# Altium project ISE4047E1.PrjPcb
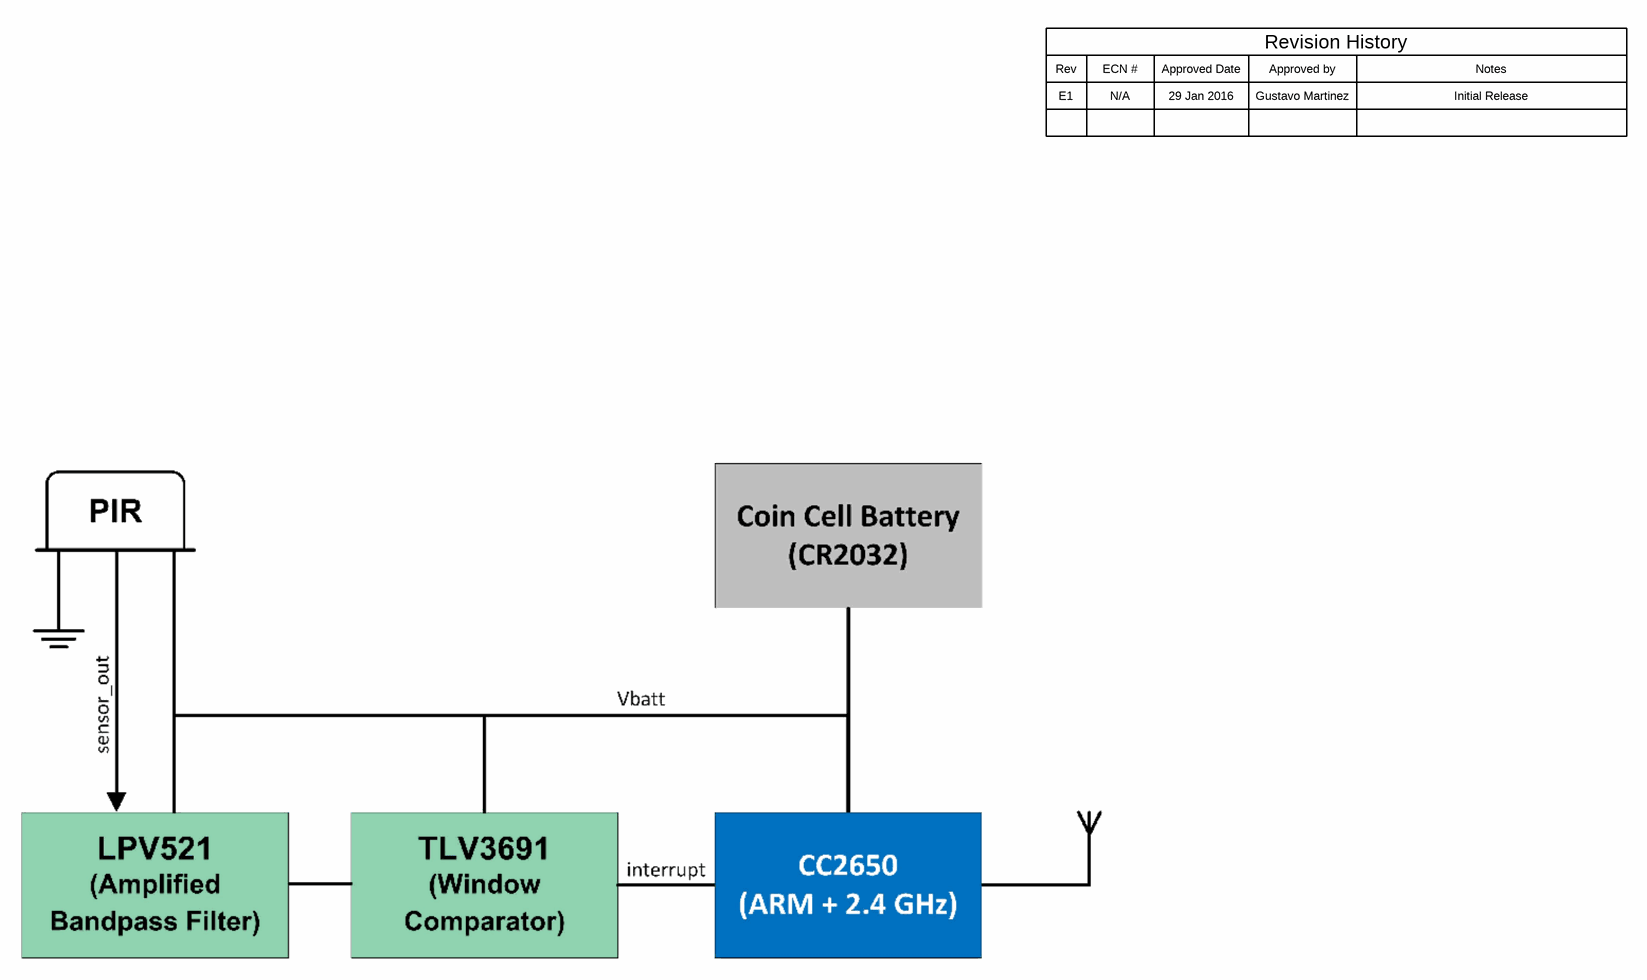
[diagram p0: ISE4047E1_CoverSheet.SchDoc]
CopyrightYear: 2016; EVM_Orderable: N/A; PCB_Layout: Krypton Solutions; PCB_Rev: E1; PRJ_Customer: Public Release; PRJ_Engineer: Gustavo Martinez; PRJ_Number: ISE4047; PRJ_Title: Wireless PIR Motion Detector w/ BLE Connectivity; SCH_Rev: E1; TechSupport: http://www.ti.com/support; TID: TIDA-00759
4 sheets, 131 parts. Net scope: global (net labels, ports and power ports of the same name join across sheets).
Board file: ISE4047E1_TID.PcbDoc
Sheets:
  ISE4047E1_CoverSheet.SchDoc
  ISE4047E1_POWER_PIR.SchDoc
  ISE4047E1_MCU.SchDoc
  ISE4047E1_TID_Hardware.SchDoc

## Sheet ISE4047E1_CoverSheet.SchDoc: Cover Sheet
size 431 x 279 mm; Date: Not shown in title block; ApprovedBy: Not shown in title block; CheckedBy: Not shown in title block; Author: Not shown in title block; CompanyName: Not shown in title block; DrawnBy: Gustavo Martinez; Engineer: Not shown in title block; Organization: Not shown in title block; Address1: Not shown in title block; Address2: Not shown in title block; Address3: Not shown in title block; Address4: Not shown in title block; DocumentNumber: 1; Revision: Use project parameter SCH_Rev; SheetNumber: 1; SheetTotal: 4; PageSetup: Record=PageOptions¦CenterHorizontal=True¦CenterVertical=True¦PrintScale=0.64¦XCorrection=1.00¦YCorrection=1.00¦PrintKind=0¦BorderSize=5000000¦LeftOffset=0¦BottomOffset=0¦Orientation=2¦PaperLength=1000¦PaperWidth=1000¦Scale=100¦PaperSource=15¦PrintQuality=1200¦MediaType=1¦DitherType=10¦PrintScaleMode=1¦PaperKind=Letter¦PaperIndex=1

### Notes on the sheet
- Rev
- E1
- ECN #
- N/A
- Approved Date
- 29 Jan 2016
- Approved by
- Gustavo Martinez
- Revision History
- Notes
- Initial Release

## Sheet ISE4047E1_POWER_PIR.SchDoc: Power and PIR Sensor
size 431 x 279 mm; Date: Not shown in title block; ApprovedBy: Not shown in title block; CheckedBy: Not shown in title block; Author: Not shown in title block; CompanyName: Not shown in title block; DrawnBy: David Stout; Engineer: David Stout; Organization: Not shown in title block; Address1: Not shown in title block; Address2: Not shown in title block; Address3: Not shown in title block; Address4: Not shown in title block; DocumentNumber: 1; Revision: Use project parameter SCH_Rev; SheetNumber: 2; SheetTotal: 4; PageSetup: Record=PageOptions¦CenterHorizontal=True¦CenterVertical=True¦PrintScale=0.62¦XCorrection=1.00¦YCorrection=1.00¦PrintKind=0¦BorderSize=5000000¦LeftOffset=0¦BottomOffset=0¦Orientation=2¦PaperLength=1000¦PaperWidth=1000¦Scale=100¦PaperSource=15¦PrintQuality=600¦MediaType=1¦DitherType=10¦PrintScaleMode=1¦PaperKind=Letter (8.5 x 11")¦PaperIndex=1
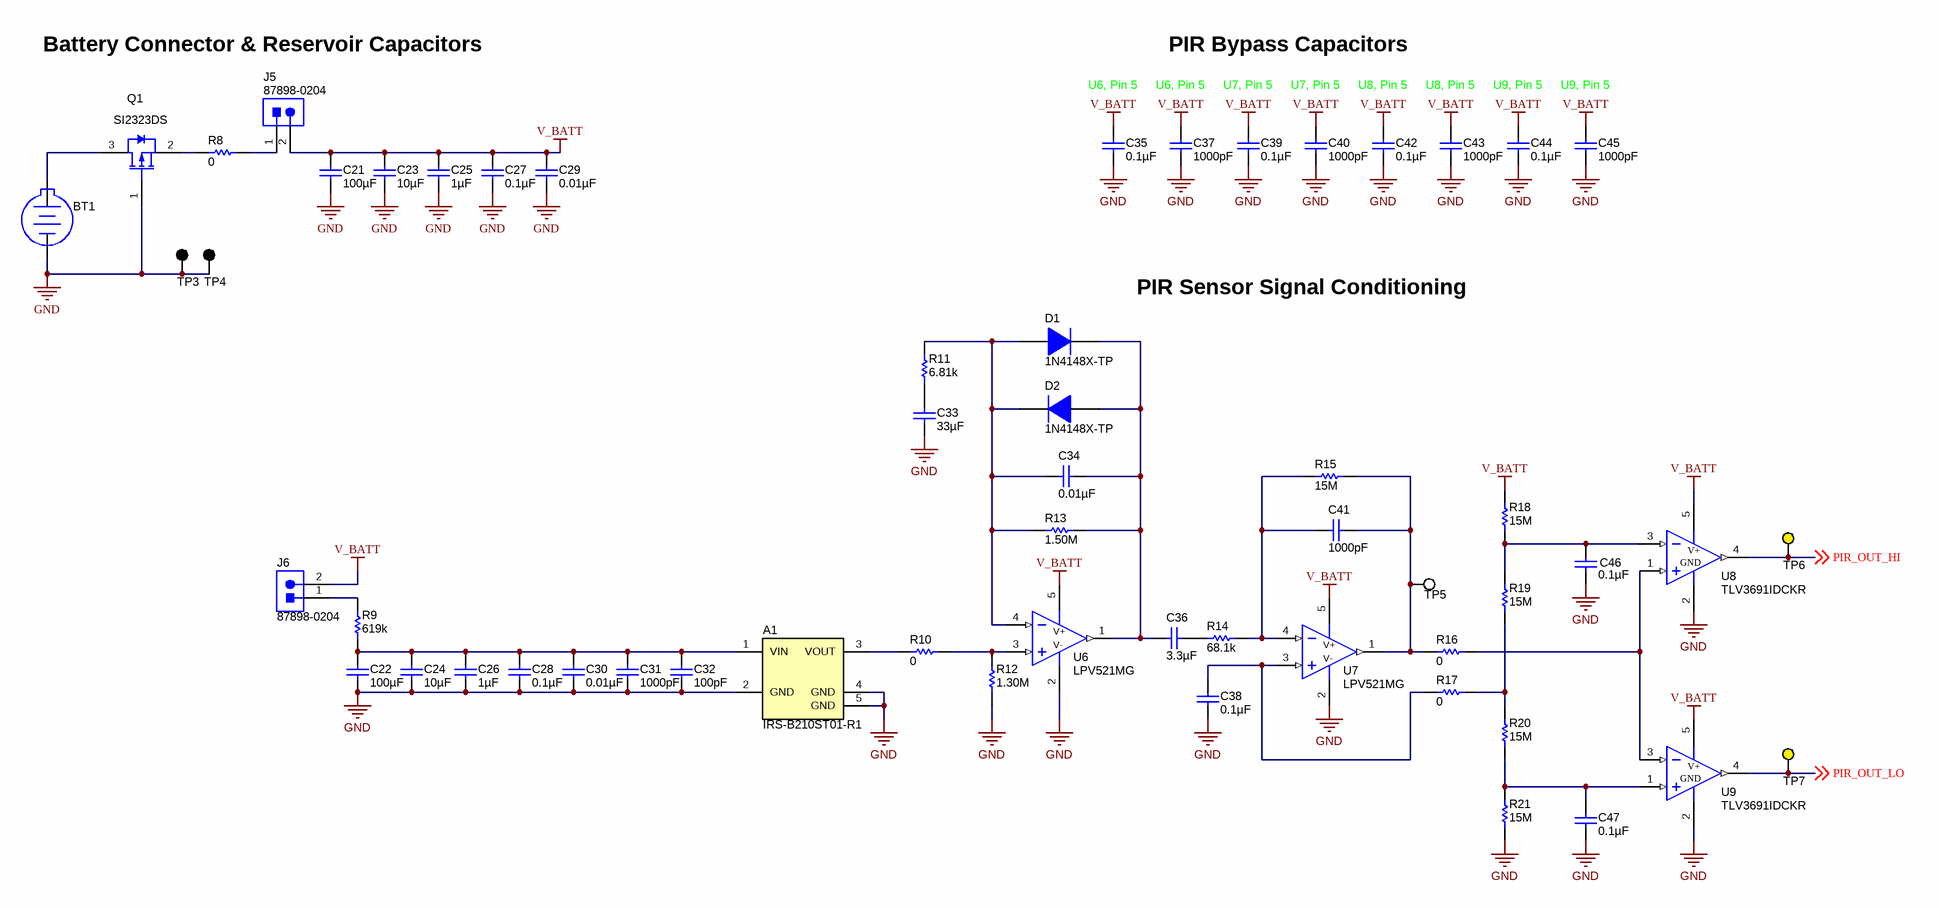
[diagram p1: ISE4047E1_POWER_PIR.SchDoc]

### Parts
A1  IRS-B210ST01-R1  [Murata_IRS-B210ST01]
BT1  BS-7  [BAT_BS-7]  (value not drawn)
C21  ValueDisplayed: 100µF  [1206_190]  (hidden comment: C3216X5R1A107M160AC)
C22  ValueDisplayed: 100µF  [1206_190]  (hidden comment: C3216X5R1A107M160AC)
C23  ValueDisplayed: 10µF  [0603]  (hidden comment: C1608X5R0J106M)
C24  ValueDisplayed: 10µF  [0402]  (hidden comment: GRM155R60J106ME44D)
C25  ValueDisplayed: 1µF  [0603]  (hidden comment: C1608X7R1C105K)
C26  ValueDisplayed: 1µF  [0402]  (hidden comment: C1005X5R1A105K050BB)
C27  ValueDisplayed: 0.1µF  [0402]  (hidden comment: C1005X7R1H104K050BB)
C28  ValueDisplayed: 0.1µF  [0402]  (hidden comment: C1005X7R1H104K050BB)
C29  ValueDisplayed: 0.01µF  [0402]  (hidden comment: C1005X7R1C103K050BA)
C30  ValueDisplayed: 0.01µF  [0402]  (hidden comment: C1005X7R1C103K050BA)
C31  ValueDisplayed: 1000pF  [0402]  (hidden comment: C1005X7R1H102K)
C32  ValueDisplayed: 100pF  [0402]  (hidden comment: C0402C101J3GACTU)
C33  ValueDisplayed: 33µF  [0805_HV]  (hidden comment: C2012X5R1A336M125AC)
C34  ValueDisplayed: 0.01µF  [0402]  (hidden comment: C1005X7R1E103K)
C35  ValueDisplayed: 0.1µF  [0402]  (hidden comment: C1005X7R1H104K)
C36  ValueDisplayed: 3.3µF  [0402]  (hidden comment: C1005X5R1A335K050BC)
C37  ValueDisplayed: 1000pF  [0402]  (hidden comment: C1005X7R1H102K)
C38  ValueDisplayed: 0.1µF  [0402]  (hidden comment: C1005X7R1H104K)
C39  ValueDisplayed: 0.1µF  [0402]  (hidden comment: C1005X7R1H104K)
C40  ValueDisplayed: 1000pF  [0402]  (hidden comment: C1005X7R1H102K)
C41  ValueDisplayed: 1000pF  [0402]  (hidden comment: C1005C0G1E102J)
C42  ValueDisplayed: 0.1µF  [0402]  (hidden comment: C1005X7R1H104K)
C43  ValueDisplayed: 1000pF  [0402]  (hidden comment: C1005X7R1H102K)
C44  ValueDisplayed: 0.1µF  [0402]  (hidden comment: C1005X7R1H104K)
C45  ValueDisplayed: 1000pF  [0402]  (hidden comment: C1005X7R1H102K)
C46  ValueDisplayed: 0.1µF  [0402]  (hidden comment: C1005X7R1H104K)
C47  ValueDisplayed: 0.1µF  [0402]  (hidden comment: C1005X7R1H104K)
D1  1N4148X-TP  [SOD-523]
D2  1N4148X-TP  [SOD-523]
J5  87898-0204  [Molex_87898-0204]
J6  87898-0204  [Molex_87898-0204]
Q1  SI2323DS  [SOT-23]
R8  ValueDisplayed: 0  [0805_HV]  (hidden comment: CRCW08050000Z0EA)
R9  ValueDisplayed: 619k  [0402]  (hidden comment: CRCW0402619KFKED)
R10  ValueDisplayed: 0  [0402]  (hidden comment: CRCW04020000Z0ED)
R11  ValueDisplayed: 6.81k  [0402]  (hidden comment: CRCW04026K81FKED)
R12  ValueDisplayed: 1.30M  [0402]  (hidden comment: CRCW04021M30FKED)
R13  ValueDisplayed: 1.50M  [0402]  (hidden comment: CRCW04021M50FKED)
R14  ValueDisplayed: 68.1k  [0402]  (hidden comment: CRCW040268K1FKED)
R15  ValueDisplayed: 15M  [0805_HV]  (hidden comment: RMCF0805JT15M0)
R16  ValueDisplayed: 0  [0402]  (hidden comment: CRCW04020000Z0ED)
R17  ValueDisplayed: 0  [0402]  (hidden comment: CRCW04020000Z0ED)
R18  ValueDisplayed: 15M  [0805_HV]  (hidden comment: RMCF0805JT15M0)
R19  ValueDisplayed: 15M  [0805_HV]  (hidden comment: RMCF0805JT15M0)
R20  ValueDisplayed: 15M  [0805_HV]  (hidden comment: RMCF0805JT15M0)
R21  ValueDisplayed: 15M  [0805_HV]  (hidden comment: RMCF0805JT15M0)
TP3  5001  [Keystone5001]  (value not drawn)
TP4  5001  [Keystone5001]  (value not drawn)
TP5  5015  [Testpoint_Keystone_Miniature]  (value not drawn)
TP6  5004  [Keystone5004]  (value not drawn)
TP7  5004  [Keystone5004]  (value not drawn)
U6  LPV521MG  [DCK0005A_N]
U7  LPV521MG  [DCK0005A_N]
U8  TLV3691IDCKR  [DCK0005A_N]
U9  TLV3691IDCKR  [DCK0005A_N]

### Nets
GND: A1.2(GND) A1.4(GND) A1.5(GND) BT1.2(-) C21.2 C22.2 C23.2 C24.2 C25.2 C26.2 C27.2 C28.2 C29.2 C30.2 C31.2 C32.2 C33.2 C35.1 C37.2 C38.2 C39.1 C40.2 C42.1 C43.2 C44.1 C45.2 C46.2 C47.2 Q1.1(G) R12.1 R21.1 TP3.1 TP4.1 U6.2(V-) U7.2(V-) U8.2(GND) U9.2(GND)
V_BATT: C21.1 C23.1 C25.1 C27.1 C29.1 C35.2 C37.1 C39.2 C40.1 C42.2 C43.1 C44.2 C45.1 J5.2 J6.2 R18.2 U6.5(V+) U7.5(V+) U8.5(V+) U9.5(V+)
PIR_OUT_HI: TP6.1 U8.4(OUT) ; off-sheet PIR_OUT_HI
PIR_OUT_LO: TP7.1 U9.4(OUT) ; off-sheet PIR_OUT_LO
NetA1_1: A1.1(VIN) C22.1 C24.1 C26.1 C28.1 C30.1 C31.1 C32.1 R9.1
NetA1_3: A1.3(VOUT) R10.1
NetBT1_1: BT1.1(+) Q1.3(D)
NetC33_1: C33.1 R11.1
NetC34_1: C34.1 C36.2 D1.1(K) D2.2(A) R13.2 U6.1(OUT)
NetC34_2: C34.2 D1.2(A) D2.1(K) R11.2 R13.1 U6.4(IN-)
NetC36_1: C36.1 R14.1
NetC38_1: C38.1 R17.1 U7.3(IN+)
NetC41_1: C41.1 R15.2 R16.1 TP5.1 U7.1(OUT)
NetC41_2: C41.2 R14.2 R15.1 U7.4(IN-)
NetC46_1: C46.1 R18.1 R19.2 U8.3(IN-)
NetC47_1: C47.1 R20.1 R21.2 U9.1(IN+)
NetJ5_1: J5.1 R8.2
NetJ6_1: J6.1 R9.2
NetQ1_2: Q1.2(S) R8.1
NetR10_2: R10.2 R12.2 U6.3(IN+)
NetR16_2: R16.2 U8.1(IN+) U9.3(IN-)
NetR17_2: R17.2 R19.1 R20.2

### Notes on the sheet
- Battery Connector & Reservoir Capacitors
- PIR Bypass Capacitors
- U6, Pin 5
- U7, Pin 5
- U8, Pin 5
- U9, Pin 5
- PIR Sensor Signal Conditioning

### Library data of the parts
A1 = IRS-B210ST01-R1: Pyroelectric Infrared Sensors for Reflow Soldering, 3.6mVp-p, SMD; Manufacturer: MuRata; SymbolCreator: Altium; CompType: SENSOR
BT1 = BS-7: Battery Holder, CR2032, Retainer clip, TH; Manufacturer: Memory Protection Devices; SymbolCreator: a0412235
C21 C22 = C3216X5R1A107M160AC: CAP, CERM, 100 µF, 10 V, +/- 20%, X5R, 1206_190; Manufacturer: TDK; Polarized: N; CompType: Capacitor; Value: 100uF; U/M: EA; Cap_F: 0.0001; Tolerance_%: 20; Value1: Unknown; VDC_V: 10; Value2: 10V; TaMin_C: -55; TaMax_C: 85; Cap_Case: 1206; AEC Category: Q200
C23 = C1608X5R0J106M: CAP, CERM, 10 µF, 6.3 V, +/- 20%, X5R, 0603; Manufacturer: TDK; Polarized: N; CompType: Capacitor; Value: 10uF; U/M: EA; Cap_F: 0.00001; Tolerance_%: 20; ESR_ohm: 0.005; Value1: 0.005 ohm; VDC_V: 6.3; Value2: 6.3V; IRMS_A: 1.9; TaMin_C: -25; TaMax_C: 85; AEC Category: Q200
C24 = GRM155R60J106ME44D: CAP, CERM, 10 µF, 6.3 V, +/- 20%, X5R, 0402; Manufacturer: MuRata; Polarized: N; CompType: Capacitor; Value: 10uF; U/M: EA; Cap_F: 0.00001; Tolerance_%: 20; Value1: Unknown; VDC_V: 6.3; Value2: 6.3V; TaMin_C: -55; TaMax_C: 85; AEC Category: Q200
C25 = C1608X7R1C105K: CAP, CERM, 1 µF, 16 V, +/- 10%, X7R, 0603; Manufacturer: TDK; Polarized: N; CompType: Capacitor; Value: 1uF; U/M: EA; Cap_F: 0.000001; Tolerance_%: 10; ESR_ohm: 0.0057; Value1: 0.0057 ohm; VDC_V: 16; Value2: 16V; TaMin_C: -55; TaMax_C: 125; AEC Category: Q200
C26 = C1005X5R1A105K050BB: CAP, CERM, 1 µF, 10 V, +/- 10%, X5R, 0402; Manufacturer: TDK; Polarized: N; CompType: Capacitor; Value: 1uF; U/M: EA; Cap_F: 0.000001; Tolerance_%: 10; Value1: Unknown; Value2: 10V; TaMin_C: -55; TaMax_C: 85; AEC Category: Q200
C27 C28 = C1005X7R1H104K050BB: CAP, CERM, 0.1 µF, 50 V, +/- 10%, X7R, 0402; Manufacturer: TDK; Polarized: N; CompType: Capacitor; Value: 0.1uF; U/M: EA; Cap_F: 0.0000001; Tolerance_%: 10; Value1: Unknown; VDC_V: 50; Value2: 50V; TaMin_C: -55; TaMax_C: 125; AEC Category: Q200
C29 C30 = C1005X7R1C103K050BA: CAP, CERM, 0.01 µF, 16 V, +/- 10%, X7R, 0402; Manufacturer: TDK; Polarized: N; CompType: Capacitor; Value: 0.01uF; U/M: EA; Cap_F: 0.00000001; Tolerance_%: 10; ESR_ohm: 0.0623; Value1: 0.0623 ohm; VDC_V: 16; Value2: 16V; TaMin_C: -55; TaMax_C: 125; AEC Category: Q200
C31 C37 C40 C43 C45 = C1005X7R1H102K: CAP, CERM, 1000 pF, 50 V, +/- 10%, X7R, 0402; Manufacturer: TDK; Polarized: N; CompType: Capacitor; Value: 1000pF; U/M: EA; Cap_F: 0.000000001; Tolerance_%: 10; ESR_ohm: 0.2381; Value1: 0.2381 ohm; VDC_V: 50; Value2: 50V; TaMin_C: -55; TaMax_C: 125; AEC Category: Q200
C32 = C0402C101J3GACTU: CAP, CERM, 100 pF, 25 V, +/- 5%, C0G/NP0, 0402; Manufacturer: Kemet; Polarized: N; CompType: Capacitor; Value: 100pF; U/M: EA; Cap_F: 0.0000000001; Tolerance_%: 5; Value1: Unknown; VDC_V: 25; Value2: 25V; TaMin_C: -55; TaMax_C: 125; AEC Category: Q200
C33 = C2012X5R1A336M125AC: CAP, CERM, 33 µF, 10 V, +/- 20%, X5R, 0805; Manufacturer: TDK; Polarized: N; CompType: Capacitor; Value: 33uF; U/M: EA; Cap_F: 0.000033; Tolerance_%: 20; Value1: Unknown; VDC_V: 10; Value2: 10V; TaMin_C: -55; TaMax_C: 85; Cap_Case: 0805; AEC Category: Q200
C34 = C1005X7R1E103K: CAP, CERM, 0.01 µF, 25 V, +/- 10%, X7R, 0402; Manufacturer: TDK; Polarized: N; CompType: Capacitor; Value: 0.01uF; U/M: EA; Cap_F: 0.00000001; Tolerance_%: 10; ESR_ohm: 0.0623; Value1: 0.0623 ohm; VDC_V: 25; Value2: 25V; TaMin_C: -55; TaMax_C: 125; AEC Category: Q200
C35 C38 C39 C42 C44 C46 C47 = C1005X7R1H104K: CAP, CERM, 0.1 µF, 50 V, +/- 10%, X7R, 0402; Manufacturer: TDK; Polarized: N; CompType: Capacitor; Value: 0.1uF; U/M: EA; Cap_F: 0.0000001; Tolerance_%: 10; Value1: Unknown; VDC_V: 50; Value2: 50V; TaMin_C: -55; TaMax_C: 125; AEC Category: Q200
C36 = C1005X5R1A335K050BC: CAP, CERM, 3.3 µF, 10 V, +/- 10%, X5R, 0402; Manufacturer: TDK; Polarized: N; CompType: Capacitor; Value: 3.3uF; U/M: EA; Cap_F: 0.0000033; Tolerance_%: 10; Value1: Unknown; Value2: 10V; TaMin_C: -55; TaMax_C: 85; AEC Category: Q200
C41 = C1005C0G1E102J: CAP, CERM, 1000 pF, 25 V, +/- 5%, C0G/NP0, 0402; Manufacturer: TDK; Polarized: N; CompType: Capacitor; Value: 1000pF; U/M: EA; Cap_F: 0.000000001; Tolerance_%: 5; Value1: Unknown; VDC_V: 25; Value2: 25V; TaMin_C: -55; TaMax_C: 125; AEC Category: Q200
D1 D2 = 1N4148X-TP: Diode, Switching, 75 V, 0.3 A, SOD-523; Manufacturer: Micro Commercial Components; U/M: EA; Vf_V: 1.25; Value: 75V; Value1: 0.3A; Value2: 1.25V; Io_A: 0.3; Vr_V: 75; TJmax_C: 150; AEC Category: Q101
J5 J6 = 87898-0204: Header, 2.54 mm, 2x1, Gold, R/A, SMT; Manufacturer: Molex; SymbolCreator: a0412235; U/M: EA
Q1 = SI2323DS: MOSFET, P-CH, -20 V, -3.7 A, SOT-23; Manufacturer: Vishay-Siliconix; Alternate Manufacturer: None; U/M: EA; ChType: P; Value: -20V; Value1: 0.031 ohm; Rdson45_ohm: 0.031; Value2: 12.5 nC; QgTyp_nC: 12.5; Vgs_V: -8; AEC Category: Q101
R8 = CRCW08050000Z0EA: RES, 0, 5%, 0.125 W, 0805; Manufacturer: Vishay-Dale; CompType: Resistor; Value: 0; Value_Code: 0000; Tolerance_%: 5; Power_W: 0.125; Value2: 0.125W; VDC_V: 150; TempCo: 200 ppm/C; EIA_Code: E24; U/M: EA; AEC Category: Q200
R9 = CRCW0402619KFKED: RES, 619 k, 1%, 0.063 W, 0402; Manufacturer: Vishay-Dale; CompType: Resistor; Value: 619k; Res_ohm: 619000; Tolerance_%: 1; Power_W: 0.063; Value2: 0.063W; VDC_V: 50; TempCo: 100 ppm/C; EIA_Code: E96; U/M: EA; AEC Category: Q200
R10 R16 R17 = CRCW04020000Z0ED: RES, 0, 5%, 0.063 W, 0402; Manufacturer: Vishay-Dale; CompType: Resistor; Value: 0; Value_Code: 0000; Tolerance_%: 5; Power_W: 0.063; Value2: 0.063W; VDC_V: 50; TempCo: 200 ppm/C; EIA_Code: E24; U/M: EA; AEC Category: Q200
R11 = CRCW04026K81FKED: RES, 6.81 k, 1%, 0.063 W, 0402; Manufacturer: Vishay-Dale; CompType: Resistor; Value: 6.81k; Res_ohm: 6810; Value_Code: 6k81; Tolerance_%: 1; Power_W: 0.063; Value2: 0.063W; VDC_V: 50; TempCo: 100 ppm/C; EIA_Code: E96; U/M: EA; AEC Category: Q200
R12 = CRCW04021M30FKED: RES, 1.30 M, 1%, 0.063 W, 0402; Manufacturer: Vishay-Dale; CompType: Resistor; Value: 1.30Meg; Res_ohm: 1300000; Value_Code: 1M30; Tolerance_%: 1; Power_W: 0.063; Value2: 0.063W; VDC_V: 50; TempCo: 100 ppm/C; EIA_Code: E96; U/M: EA; AEC Category: Q200
R13 = CRCW04021M50FKED: RES, 1.50 M, 1%, 0.063 W, 0402; Manufacturer: Vishay-Dale; CompType: Resistor; Value: 1.50Meg; Res_ohm: 1500000; Value_Code: 1M50; Tolerance_%: 1; Power_W: 0.063; Value2: 0.063W; VDC_V: 50; TempCo: 100 ppm/C; EIA_Code: E96; U/M: EA; AEC Category: Q200
R14 = CRCW040268K1FKED: RES, 68.1 k, 1%, 0.063 W, 0402; Manufacturer: Vishay-Dale; CompType: Resistor; Value: 68.1k; Res_ohm: 68100; Value_Code: 68k1; Tolerance_%: 1; Power_W: 0.063; Value2: 0.063W; VDC_V: 50; TempCo: 100 ppm/C; EIA_Code: E96; U/M: EA; AEC Category: Q200
R15 R18-R21 = RMCF0805JT15M0: RES, 15 M, 5%, 0.125 W, AEC-Q200 Grade 0, 0805; Manufacturer: Stackpole Electronics Inc; CompType: Resistor; Value: 15Meg; Res_ohm: 15000000; Value_Code: 15M0; Tolerance_%: 5; Power_W: 0.125; Value2: 0.125W; VDC_V: 75; TempCo: 200 ppm/C; U/M: EA; AEC Category: Q200; AEC Qualified: Y; AEC Grade: 0
TP3 TP4 = 5001: Test Point, Miniature, Black, TH; Manufacturer: Keystone; CompType: Test Point Loop; U/M: EA
TP5 = 5015: Test Point, Miniature, SMT; Manufacturer: Keystone; CompType: Test Point Loop; U/M: EA
TP6 TP7 = 5004: Test Point, Miniature, Yellow, TH; Manufacturer: Keystone; CompType: Test Point Loop; U/M: EA
U6 U7 = LPV521MG: Nanopower 400nA, 1.8V, R-R I/O CMOS Op Amp, DCK0005A; Manufacturer: Texas Instruments; CompType: OpAmp IC
U8 U9 = TLV3691IDCKR: 0.9-V to 6.5-V, Nanopower Comparator, DCK0005A; Alternate PartNumber: TLV3691IDCKT; Manufacturer: Texas Instruments; SymbolCreator: OpAmp IC; CompType: IC; U/M: EA

## Sheet ISE4047E1_MCU.SchDoc: Wireless MCU
size 431 x 279 mm; Date: Not shown in title block; ApprovedBy: Not shown in title block; CheckedBy: Not shown in title block; Author: Not shown in title block; CompanyName: Not shown in title block; DrawnBy: Gustavo Martinez; Engineer: Not shown in title block; Organization: Not shown in title block; Address1: Not shown in title block; Address2: Not shown in title block; Address3: Not shown in title block; Address4: Not shown in title block; DocumentNumber: 1; Revision: Use project parameter SCH_Rev; SheetNumber: 3; SheetTotal: 4; PageSetup: Record=PageOptions¦CenterHorizontal=True¦CenterVertical=True¦PrintScale=1.00¦XCorrection=1.00¦YCorrection=1.00¦PrintKind=0¦BorderSize=5000000¦LeftOffset=0¦BottomOffset=0¦Orientation=2¦PaperLength=1000¦PaperWidth=1000¦Scale=100¦PaperSource=15¦PrintQuality=600¦MediaType=1¦DitherType=10¦PaperKind=Letter¦PrintScaleMode=1
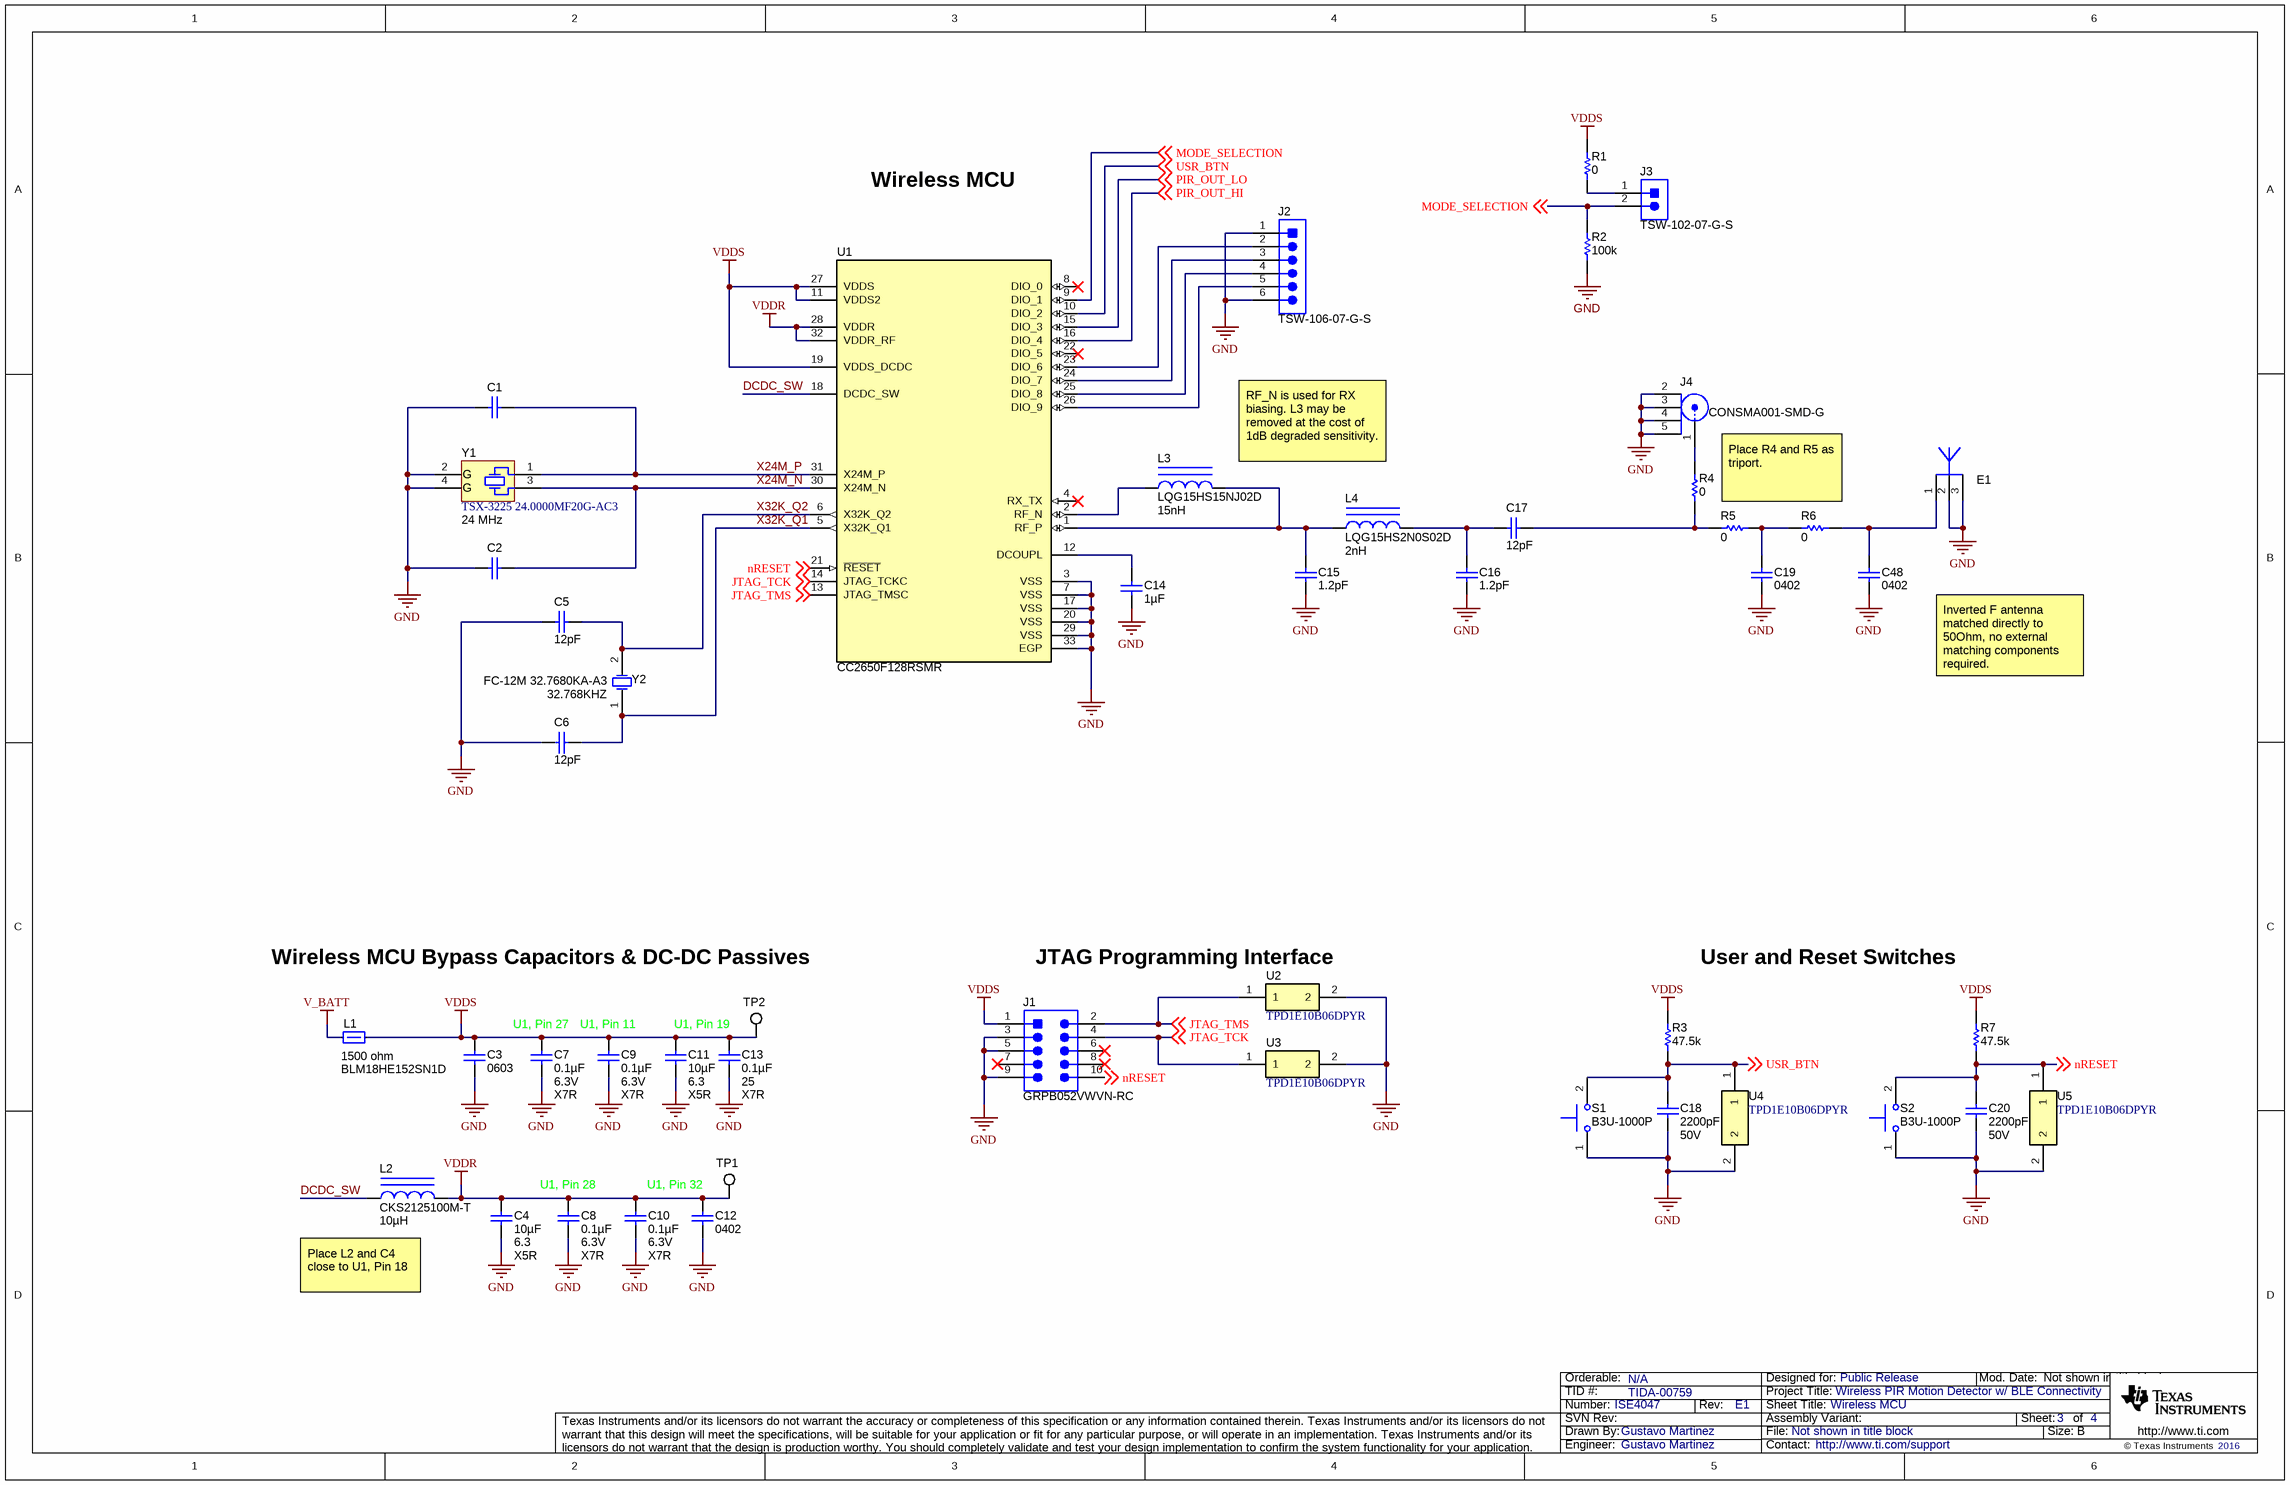
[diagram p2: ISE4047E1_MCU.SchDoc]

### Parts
C1  GRM1555C1E120JA01D  [0402]  (value not drawn)
C2  GRM1555C1E120JA01D  [0402]  (value not drawn)
C3  Used in BOM report  [0603]  (value not drawn)
C4  ValueDisplayed: 10µF  VDC_V: 6.3  TempCo: X5R  [0603]  (hidden comment: GRM188R60J106ME47D)
C5  ValueDisplayed: 12pF  [0402]  (hidden comment: GRM1555C1E120JA01D)
C6  ValueDisplayed: 12pF  [0402]  (hidden comment: GRM1555C1E120JA01D)
C7  ValueDisplayed: 0.1µF  Value2: 6.3V  TempCo: X7R  [0402S]  (hidden comment: GRM155R70J104KA01D)
C8  ValueDisplayed: 0.1µF  Value2: 6.3V  TempCo: X7R  [0402S]  (hidden comment: GRM155R70J104KA01D)
C9  ValueDisplayed: 0.1µF  Value2: 6.3V  TempCo: X7R  [0402]  (hidden comment: GRM155R70J104KA01D)
C10  ValueDisplayed: 0.1µF  Value2: 6.3V  TempCo: X7R  [0402S]  (hidden comment: GRM155R70J104KA01D)
C11  ValueDisplayed: 10µF  VDC_V: 6.3  TempCo: X5R  [0603]  (hidden comment: GRM188R60J106ME47D)
C12  PackageReference: 0402  [0402S]  (hidden comment: Used in BOM report)
C13  ValueDisplayed: 0.1µF  VDC_V: 25  TempCo: X7R  [0603]  (hidden comment: GRM188R71E104KA01D)
C14  ValueDisplayed: 1µF  [0402]  (hidden comment: GRM155R61A105KE15D)
C15  ValueDisplayed: 1.2pF  [0402S]  (hidden comment: GRM1555C1H1R2BA01D)
C16  ValueDisplayed: 1.2pF  [0402S]  (hidden comment: GRM1555C1H1R2BA01D)
C17  ValueDisplayed: 12pF  [0402S]  (hidden comment: GRM1555C1H120JA01D)
C18  ValueDisplayed: 2200pF  Value2: 50V  [0402]  (hidden comment: C1005X7R1H222K)
C19  PackageReference: 0402  [0402S]  (hidden comment: Used in BOM report)
C20  ValueDisplayed: 2200pF  Value2: 50V  [0402]  (hidden comment: C1005X7R1H222K)
C48  PackageReference: 0402  [0402S]  (hidden comment: Used in BOM report)
E1  ANTENNA_DN007A  [ANTENNA_DN007A]  (value not drawn)  (net tie)
J1  GRPB052VWVN-RC  [CONN_GRPB052VWVN-RC]
J2  TSW-106-07-G-S  [TSW-106-07-G-S]
J3  TSW-102-07-G-S  [TSW-102-07-G-S]
J4  CONSMA001-SMD-G  [Linx_CONSMA001-SMD-G]
L1  value 1500 ohm  [0603]  (hidden comment: BLM18HE152SN1D)
L2  CKS2125100M-T  ValueDisplayed: 10µH  [0805_145]
L3  LQG15HS15NJ02D  ValueDisplayed: 15nH  [IND_LQG15H]
L4  LQG15HS2N0S02D  ValueDisplayed: 2nH  [IND_LQG15H]
R1  ValueDisplayed: 0  [0402]  (hidden comment: CRCW04020000Z0ED)
R2  ValueDisplayed: 100k  [0402]  (hidden comment: CRCW0402100KFKED)
R3  ValueDisplayed: 47.5k  [0402]  (hidden comment: CRCW040247K5FKED)
R4  ValueDisplayed: 0  [0402S]  (hidden comment: CRCW04020000Z0ED)
R5  ValueDisplayed: 0  [0402S]  (hidden comment: CRCW04020000Z0ED)
R6  ValueDisplayed: 0  [0402S]  (hidden comment: CRCW04020000Z0ED)
R7  ValueDisplayed: 47.5k  [0402]  (hidden comment: CRCW040247K5FKED)
S1  B3U-1000P  [SW_B3U-1000P]
S2  B3U-1000P  [SW_B3U-1000P]
TP1  5015  [Testpoint_Keystone_Miniature]  (value not drawn)
TP2  5015  [Testpoint_Keystone_Miniature]  (value not drawn)
U1  CC2650F128RSMR  [RSM0032B]
U2  TPD1E10B06DPYR  [DPY0002A]
U3  TPD1E10B06DPYR  [DPY0002A]
U4  TPD1E10B06DPYR  [DPY0002A]
U5  TPD1E10B06DPYR  [DPY0002A]
Y1  TSX-3225 24.0000MF20G-AC3  Frequency: 24 MHz  [EPSON_TSX-3225]
Y2  FC-12M 32.7680KA-A3  Frequency: 32.768KHZ  [Epson_FC-12M]

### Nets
GND: C1.1 C2.1 C3.2 C4.1 C5.2 C6.2 C7.2 C8.2 C9.2 C10.2 C11.1 C12.2 C13.1 C14.2 C15.2 C16.2 C18.1 C19.1 C20.1 C48.1 E1.2 E1.3 J1.3 J1.5 J1.9 J2.1 J2.6 J4.2 J4.3 J4.4 J4.5 R2.1 S1.1 S2.1 U1.3(VSS) U1.7(VSS) U1.17(VSS) U1.20(VSS) U1.29(VSS) U1.33(EGP) U2.2 U3.2 U4.2 U5.2 Y1.2(GND) Y1.4(GND)
V_BATT: L1.1
VDDR: C4.2 C8.1 C10.1 C12.1 L2.2 TP1.1 U1.28(VDDR) U1.32(VDDR_RF)
VDDS: C3.1 C7.1 C9.1 C11.2 C13.2 J1.1 L1.2 R1.2 R3.2 R7.2 TP2.1 U1.11(VDDS2) U1.19(VDDS_DCDC) U1.27(VDDS)
DCDC_SW: L2.1 U1.18(DCDC_SW)
JTAG_TCK: J1.4 U1.14(JTAG_TCKC) U3.1 ; off-sheet JTAG_TCK
JTAG_TMS: J1.2 U1.13(JTAG_TMSC) U2.1 ; off-sheet JTAG_TMS
MODE_SELECTION: J3.2 R2.2 U1.9(DIO_1) ; off-sheet MODE_SELECTION
nRESET: C20.2 J1.10 R7.1 S2.2 U1.21(~{RESET}) U5.1 ; off-sheet nRESET
PIR_OUT_HI: U1.16(DIO_4) ; off-sheet PIR_OUT_HI
PIR_OUT_LO: U1.15(DIO_3) ; off-sheet PIR_OUT_LO
USR_BTN: C18.2 R3.1 S1.2 U1.10(DIO_2) U4.1 ; off-sheet USR_BTN
X24M_N: C2.2 U1.30(X24M_N) Y1.3
X24M_P: C1.2 U1.31(X24M_P) Y1.1
X32K_Q1: C6.1 U1.5(X32K_Q1) Y2.1(OSC1)
X32K_Q2: C5.1 U1.6(X32K_Q2) Y2.2(OSC2)
NetC14_1: C14.1 U1.12(DCOUPL)
NetC15_1: C15.1 L3.2 L4.1 U1.1(RF_P)
NetC16_1: C16.1 C17.2 L4.2
NetC17_1: C17.1 R4.1 R5.1
NetC19_2: C19.2 R5.2 R6.1
NetC48_2: C48.2 E1.1 R6.2
NetJ2_2: J2.2 U1.23(DIO_6)
NetJ2_3: J2.3 U1.24(DIO_7)
NetJ2_4: J2.4 U1.25(DIO_8)
NetJ2_5: J2.5 U1.26(DIO_9)
NetJ3_1: J3.1 R1.1
NetJ4_1: J4.1 R4.2
NetL3_1: L3.1 U1.2(RF_N)

Not connected (* = marked no-connect by the designer): J1 6* 7* 8*; U1 4(RX_TX)* 8(DIO_0)* 22(DIO_5)*

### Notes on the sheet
- Wireless MCU
- (near L3) RF_N is used for RX biasing. L3 may be removed at the cost of 1dB degraded sensitivity.
- Place R4 and R5 as triport.
- Inverted F antenna matched directly to 50Ohm, no external matching components required.
- Wireless MCU Bypass Capacitors & DC-DC Passives
- (near U2) JTAG Programming Interface
- User and Reset Switches
- (near C7) U1, Pin 27
- (near C9) U1, Pin 11
- U1, Pin 19
- (near C8) U1, Pin 28
- U1, Pin 32
- (near L2) Place L2 and C4 close to U1, Pin 18

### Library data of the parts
C1 C2 C5 C6 = GRM1555C1E120JA01D: CAP, CERM, 12 pF, 25 V, +/- 5%, C0G/NP0, 0402; Manufacturer: MuRata; Polarized: N; CompType: Capacitor; Value: 12pF; U/M: EA; Cap_F: 0.000000000012; Tolerance_%: 5; Value1: Unknown; VDC_V: 25; Value2: 25V; TaMin_C: -55; TaMax_C: 125; AEC Category: Q200
C3 C12 C19 C48 = Capacitor: CAP, CERM, xxxF, xxV, [TempCo], xx%, [PackageReference]; Polarized: N; U/M: EA
C4 C11 = GRM188R60J106ME47D: CAP, CERM, 10 µF, 6.3 V, +/- 20%, X5R, 0603; Manufacturer: MuRata; Polarized: N; CompType: Capacitor; Value: 10uF; U/M: EA; Cap_F: 0.00001; Tolerance_%: 20; ESR_ohm: 0.009; Value1: 0.009 ohm; Value2: 6.3V; IRMS_A: 2.74; TaMin_C: -55; TaMax_C: 125; AEC Category: Q200
C7 C8 C10 = GRM155R70J104KA01D: CAP, CERM, 0.1 µF, 6.3 V, +/- 10%, X7R, 0402; Manufacturer: MuRata; Polarized: N; CompType: Capacitor; Value: 0.1uF; U/M: EA; Cap_F: 0.0000001; Tolerance_%: 10; Value1: Unknown; VDC_V: 6.3; TaMin_C: -55; TaMax_C: 125; Cap_Case: 0402
C9 = GRM155R70J104KA01D: CAP, CERM, 0.1 µF, 6.3 V, +/- 10%, X7R, 0402; Manufacturer: MuRata; Polarized: N; CompType: Capacitor; Value: 0.1uF; U/M: EA; Cap_F: 0.0000001; Tolerance_%: 10; Value1: Unknown; VDC_V: 6.3; TaMin_C: -55; TaMax_C: 125
C13 = GRM188R71E104KA01D: CAP, CERM, 0.1 µF, 25 V, +/- 10%, X7R, 0603; Manufacturer: MuRata; Polarized: N; CompType: Capacitor; Value: 0.1uF; U/M: EA; Cap_F: 0.0000001; Tolerance_%: 10; Value1: Unknown; Value2: 25V; TaMin_C: -55; TaMax_C: 125; AEC Category: Q200
C14 = GRM155R61A105KE15D: CAP, CERM, 1 µF, 10 V, +/- 10%, X5R, 0402; Manufacturer: MuRata; Polarized: N; CompType: Capacitor; Value: 1uF; U/M: EA; Cap_F: 0.000001; Tolerance_%: 10; Value1: Unknown; Value2: 10V; TaMin_C: -55; TaMax_C: 85; AEC Category: Q200
C15 C16 = GRM1555C1H1R2BA01D: CAP, CERM, 1.2 pF, 50 V, +/- 8.3%, C0G/NP0, 0402; Manufacturer: MuRata; Polarized: N; CompType: Capacitor; Value: 1.2pF; U/M: EA; Cap_F: 0.0000000000012; Tolerance_%: 8.3; Value1: Unknown; VDC_V: 50; Value2: 50V; TaMin_C: -55; TaMax_C: 125; Cap_Case: 0402; AEC Category: Q200
C17 = GRM1555C1H120JA01D: CAP, CERM, 12 pF, 50 V, +/- 5%, C0G/NP0, 0402; Manufacturer: MuRata; Polarized: N; CompType: Capacitor; Value: 12pF; U/M: EA; Cap_F: 0.000000000012; Tolerance_%: 5; Value1: Unknown; VDC_V: 50; Value2: 50V; TaMin_C: -55; TaMax_C: 125; Cap_Case: 0402; AEC Category: Q200
C18 C20 = C1005X7R1H222K: CAP, CERM, 2200 pF, 50 V, +/- 10%, X7R, 0402; Manufacturer: TDK; Polarized: N; CompType: Capacitor; Value: 2200pF; U/M: EA; Cap_F: 0.0000000022; Tolerance_%: 10; ESR_ohm: 0.1433; Value1: 0.1433 ohm; VDC_V: 50; TaMin_C: -55; TaMax_C: 125; AEC Category: Q200
E1 = ANTENNA_DN007A: 2.4GHz PCB Antenna.  There is nothing to buy or mount.; SymbolCreator: a0412235
J1 = GRPB052VWVN-RC: Header, 50mil, 5x2, Gold, TH; Manufacturer: Sullins Connector Solutions; SymbolCreator: a0412235; U/M: EA
J2 = TSW-106-07-G-S: Header, 100mil, 6x1, Gold, TH; Manufacturer: Samtec; SymbolCreator: a0412235; U/M: EA
J3 = TSW-102-07-G-S: Header, 100mil, 2x1, Gold, TH; Manufacturer: Samtec; SymbolCreator: a0412235; U/M: EA
J4 = CONSMA001-SMD-G: Jack, SMA, PCB, Gold, SMT; Manufacturer: Linx Technologies; SymbolCreator: X0208326; U/M: EA
L1 = BLM18HE152SN1D: Ferrite Bead, 1500 ohm @ 100 MHz, 0.5 A, 0603; Manufacturer: MuRata; Imax_A: 0.5; Value1: 0.5 ohm; Value2: 0.5A; ZTyp@100MHz_Ohm: 1500
L2 = CKS2125100M-T: Inductor, Multilayer, Ferrite, 10uH, 0.11A, 0.52 ohm, SMD; Manufacturer: Taiyo Yuden; Ind_H: 10.0E-6; Imax_A: 0.11; DCR_ohm: 0.52
L3 = LQG15HS15NJ02D: Inductor, Multilayer, Air Core, 15 nH, 0.3 A, 0.32 ohm, SMD; Manufacturer: MuRata; Value: 15nH; Ind_H: 15.0E-9; Imax_A: 0.3; Irms: 0.3A @ C rise; Isat: 0.3A @ % inductance drop; DCR_ohm: 0.32; Value2: 0.3A; AEC Category: Q200
L4 = LQG15HS2N0S02D: Inductor, Multilayer, Air Core, 2 nH, 0.3 A, 0.1 ohm, SMD; Manufacturer: MuRata; Value: 2nH; Ind_H: 2.0E-9; Imax_A: 0.3; Irms: 0.3A @ C rise; Isat: 0.3A @ % inductance drop; DCR_ohm: 0.1; Value1: 0.1 ohm; Value2: 0.3A; AEC Category: Q200
R1 R4-R6 = CRCW04020000Z0ED: as R10 on sheet ISE4047E1_POWER_PIR
R2 = CRCW0402100KFKED: RES, 100 k, 1%, 0.063 W, 0402; Manufacturer: Vishay-Dale; CompType: Resistor; Value: 100k; Res_ohm: 100000; Tolerance_%: 1; Power_W: 0.063; Value2: 0.063W; VDC_V: 50; TempCo: 100 ppm/C; EIA_Code: E96; U/M: EA; AEC Category: Q200
R3 R7 = CRCW040247K5FKED: RES, 47.5 k, 1%, 0.063 W, 0402; Manufacturer: Vishay-Dale; CompType: Resistor; Res_ohm: 47500; Value: 47.5k; Value_Code: 47k5; Tolerance_%: 1; Power_W: 0.063; Value2: 0.063W; VDC_V: 50; TempCo: 100 ppm/C; EIA_Code: E96; U/M: EA; AEC Category: Q200
S1 S2 = B3U-1000P: SWITCH TACTILE SPST-NO 0.05A 12V; Manufacturer: Omron Electronic Components; SymbolCreator: a0412235; VDC_V: 12; SwitchFunction: Off-Mom; PositionCount: 1; CurrentRating_mA: 50
TP1 TP2 = 5015: as TP5 on sheet ISE4047E1_POWER_PIR
U1 = CC2650F128RSMR: Ultra low-power ARM Cortex M3 2.4 GHz Radio MCU, RSM0032B; Alternate PartNumber: CC2650F128RSMT; Manufacturer: Texas Instruments; SymbolCreator: Altium; CompType: IC; U/M: EA
U2-U5 = TPD1E10B06DPYR: ESD in 0402 Package with 10 pF Capacitance and 6 V Breakdown, 1 Channel, -40 to +125 degC, 2-pin X2SON (DPY), Green (RoHS & no Sb/Br); Manufacturer: Texas Instruments; Alternate PartNumber: Equivalent; Breakdown Voltage(Min)(V): 6; Eco-Plan: TBD; IEC 61000-4-2 Air-Gap(+/- kV): 30; IO Capacitance(Typ)(pF): 10; SubFamily: ESD Solution
Y1 = TSX-3225 24.0000MF20G-AC3: Crystal, 24 MHz, 9 pF, SMD; Manufacturer: Epson; SymbolCreator: a0412235; U/M: EA; TaMin_C: -40; TaMax_C: 85; Frequency Stability: ±20ppm
Y2 = FC-12M 32.7680KA-A3: Crystal, 32.768kHz, 12.5pF, SMD; Manufacturer: Epson; SymbolCreator: a0412235; U/M: EA; TaMin_C: -40; TaMax_C: 85; Frequency Stability: ±20ppm

## Sheet ISE4047E1_TID_Hardware.SchDoc: Hardware
size 431 x 279 mm; Date: Not shown in title block; ApprovedBy: Not shown in title block; CheckedBy: Not shown in title block; Author: Not shown in title block; CompanyName: Not shown in title block; DrawnBy: Gustavo Martinez; Engineer: Gustavo Martinez; Organization: Not shown in title block; Address1: Not shown in title block; Address2: Not shown in title block; Address3: Not shown in title block; Address4: Not shown in title block; DocumentNumber: 1; Revision: Use project parameter SCH_Rev; SheetNumber: 4; SheetTotal: 4; PageSetup: Record=PageOptions¦CenterHorizontal=True¦CenterVertical=True¦PrintScale=1.00¦XCorrection=1.00¦YCorrection=1.00¦PrintKind=0¦BorderSize=5000000¦LeftOffset=0¦BottomOffset=0¦Orientation=2¦PaperLength=1000¦PaperWidth=1000¦Scale=100¦PaperSource=15¦PrintQuality=600¦MediaType=1¦DitherType=10¦PaperKind=Letter¦PrintScaleMode=1
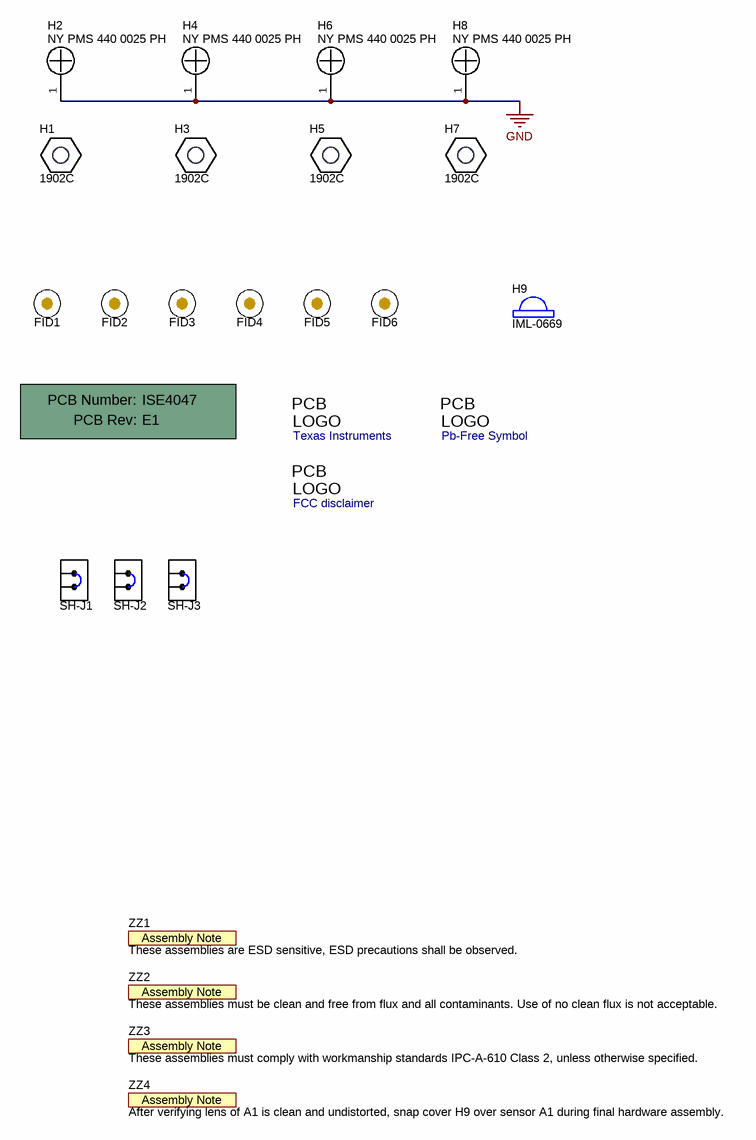
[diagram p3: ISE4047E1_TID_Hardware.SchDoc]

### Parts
!PCB1  Printed Circuit Board  (value not drawn)  (mechanical)
FID1  Fiducial  [Fiducial10-20]  (value not drawn)
FID2  Fiducial  [Fiducial10-20]  (value not drawn)
FID3  Fiducial  [Fiducial10-20]  (value not drawn)
FID4  Fiducial  [Fiducial10-20]  (value not drawn)
FID5  Fiducial  [Fiducial10-20]  (value not drawn)
FID6  Fiducial  [Fiducial10-20]  (value not drawn)
H1  1902C  [Keystone_1902C]
H2  NY PMS 440 0025 PH  [NY PMS 440 0025 PH]
H3  1902C  [Keystone_1902C]
H4  NY PMS 440 0025 PH  [NY PMS 440 0025 PH]
H5  1902C  [Keystone_1902C]
H6  NY PMS 440 0025 PH  [NY PMS 440 0025 PH]
H7  1902C  [Keystone_1902C]
H8  NY PMS 440 0025 PH  [NY PMS 440 0025 PH]
H9  IML-0669  [Murata_IML-0669]
Logo1  Texas Instruments  [TI_Symbol_Overlay_Small]  (no BOM)
Logo2  FCC disclaimer  [FCC_disclaimer_stacked]  (no BOM)
Logo3  Pb-Free Symbol  [Pb-Free_Overlay_Small]  (no BOM)
SH-J1  969102-0000-DA  [SNT-100-BK-G]  (value not drawn)
SH-J2  969102-0000-DA  [SNT-100-BK-G]  (value not drawn)
SH-J3  969102-0000-DA  [SNT-100-BK-G]  (value not drawn)
ZZ1  These assemblies are ESD sensitive, ESD precautions shall be observed.  [AssemblyNote]  (no BOM)
ZZ2  These assemblies must be clean and free from flux and all contaminants. Use of no clean flux is not acceptable.  [AssemblyNote]  (no BOM)
ZZ3  These assemblies must comply with workmanship standards IPC-A-610 Class 2, unless otherwise specified.  [AssemblyNote]  (no BOM)
ZZ4  After verifying lens of A1 is clean and undistorted, snap cover H9 over sensor A1 during final hardware assembly.  [AssemblyNote]  (no BOM)

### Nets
GND: H2.1 H4.1 H6.1 H8.1

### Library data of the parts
!PCB1 = PCB: Manufacturer: Any; PartNumber: ISE4047; SymbolCreator: a0412235
FID1-FID6 = Fiducial: Fiducial mark.  There is nothing to buy or mount.; SymbolCreator: codlsc
H1 H3 H5 H7 = 1902C: Standoff, Hex, 0.5"L #4-40 Nylon; Manufacturer: Keystone; CompType: Hardware; SymbolCreator: a0412235
H2 H4 H6 H8 = NY PMS 440 0025 PH: Machine Screw, Round, #4-40 x 1/4, Nylon, Philips panhead; Manufacturer: B&F Fastener Supply; CompType: Hardware; SymbolCreator: codlsc; U/M: EA
H9 = IML-0669: Lens, Ceiling Mount, TH; Manufacturer: MuRata; SymbolCreator: Altium
Logo1 = TI_Logo: Texas Instrument Corporate Signature; SymbolCreator: a0412235
Logo2 = FCC_disclaimer: SymbolCreator: codlsc
Logo3 = Pb-Free: SymbolCreator: a0412235
SH-J1-SH-J3 = 969102-0000-DA: Shunt, 100mil, Gold plated, Black; Manufacturer: 3M; Alternate Manufacturer: Samtec; Value: 1x2; Note: You can "mate" this to a header by matching the designator.  i.e. use SH-J3 for header J3
ZZ1-ZZ4 = AssemblyNote: SymbolCreator: codlsc

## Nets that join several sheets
GND: ISE4047E1_POWER_PIR (37 pins), ISE4047E1_MCU (46 pins), ISE4047E1_TID_Hardware (H2.1 H4.1 H6.1 H8.1)
V_BATT: ISE4047E1_POWER_PIR (20 pins), ISE4047E1_MCU (L1.1)
PIR_OUT_HI: ISE4047E1_POWER_PIR (TP6.1 U8.4), ISE4047E1_MCU (U1.16)
PIR_OUT_LO: ISE4047E1_POWER_PIR (TP7.1 U9.4), ISE4047E1_MCU (U1.15)

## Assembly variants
001: not fitted C1 C2 C3 C12 C19 C48 FID1 FID2 FID3 FID4 FID5 FID6 J2 J4 R4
